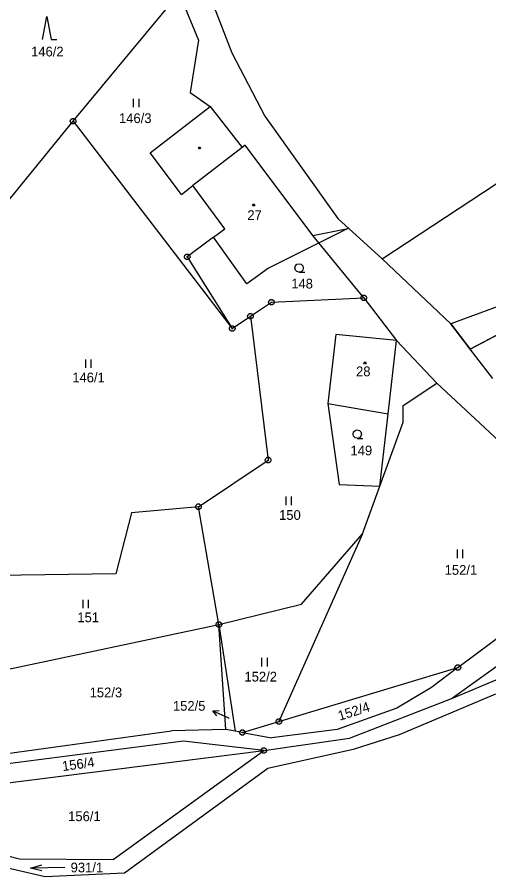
# Model space of a CAD drawing. Extents: x -580551 to -575069, y -1073031 to -1067931.
# Drawn here: x -576758.6 to -576676.1, y -1069901 to -1069750.7 of the extents above; entities that cross this region are included whole.
import ezdxf

# ---------------------------------------------------------------- set-up
doc = ezdxf.new("R2010")
doc.units = 0
for name, color, linetype in [('Druh pozemku', 7, 'Continuous'), ('Geodetické body', 7, 'Continuous'), ('Katastrální hranice', 7, 'Continuous'), ('Parcela', 7, 'Continuous'), ('Parcelní číslo', 7, 'Continuous'), ('Parcelní číslo_stavba', 7, 'Continuous'), ('Pomocná vrstva', 7, 'Continuous'), ('SR - hranice státu', 7, 'Continuous'), ('Vnitřní kresba', 7, 'Continuous'), ('Vrstva 6', 7, 'Continuous')]:
    doc.layers.add(name, color=color, linetype=linetype)

msp = doc.modelspace()

# ---------------------------------------------------------------- linework, layer by layer
at = {"layer": 'Druh pozemku'}
for p, q in [((-576738.33, -1069764.98), (-576738.33, -1069766.48)), ((-576737.33, -1069766.48), (-576737.33, -1069764.98)), ((-576746.71, -1069810.56), (-576746.71, -1069812.06)), ((-576745.71, -1069812.06), (-576745.71, -1069810.56)), ((-576711.66, -1069834.55), (-576711.66, -1069836.05)), ((-576710.66, -1069836.05), (-576710.66, -1069834.55)), ((-576681.66, -1069843.82), (-576681.66, -1069845.32)), ((-576680.66, -1069845.32), (-576680.66, -1069843.82)), ((-576747.18, -1069852.58), (-576747.18, -1069854.08)), ((-576746.18, -1069854.08), (-576746.18, -1069852.58)), ((-576715.88, -1069862.74), (-576715.88, -1069864.24)), ((-576714.88, -1069864.24), (-576714.88, -1069862.74)), ((-576750.31, -1069899.407), (-576756.31, -1069899.493))]:
    msp.add_line(p, q, dxfattribs=at)
for points in [[(-576754.19, -1069754.61), (-576753.44, -1069750.61), (-576752.69, -1069754.61), (-576751.69, -1069754.61)], [(-576709.32, -1069795.31), (-576709.7, -1069795.21), (-576709.97, -1069794.94), (-576710.07, -1069794.57), (-576709.97, -1069794.2), (-576709.7, -1069793.93), (-576709.33, -1069793.83), (-576708.96, -1069793.93), (-576708.69, -1069794.2), (-576708.59, -1069794.58), (-576708.69, -1069794.96), (-576708.96, -1069795.23), (-576709.34, -1069795.33), (-576708.34, -1069795.33)], [(-576699.14, -1069824.35), (-576699.52, -1069824.25), (-576699.79, -1069823.98), (-576699.89, -1069823.61), (-576699.79, -1069823.24), (-576699.52, -1069822.97), (-576699.15, -1069822.87), (-576698.78, -1069822.97), (-576698.51, -1069823.24), (-576698.41, -1069823.62), (-576698.51, -1069824), (-576698.78, -1069824.27), (-576699.16, -1069824.37), (-576698.16, -1069824.37)], [(-576754.303, -1069899.964), (-576756.31, -1069899.493), (-576754.317, -1069898.964)]]:
    msp.add_lwpolyline(points, dxfattribs=at)
for points in [[(-576726.65, -1069773.46), (-576726.56, -1069773.61), (-576726.65, -1069773.76), (-576726.83, -1069773.76), (-576726.92, -1069773.61), (-576726.83, -1069773.46)], [(-576717.18, -1069783.4), (-576717.09, -1069783.55), (-576717.18, -1069783.7), (-576717.36, -1069783.7), (-576717.45, -1069783.55), (-576717.36, -1069783.4)], [(-576697.71, -1069811.02), (-576697.62, -1069811.17), (-576697.71, -1069811.32), (-576697.89, -1069811.32), (-576697.98, -1069811.17), (-576697.89, -1069811.02)]]:
    msp.add_lwpolyline(points, close=True, dxfattribs=at)
at = {"layer": 'Geodetické body'}
for p, q in [((-576748.98, -1069768.89), (-576748.74, -1069768.89)), ((-576729, -1069792.64), (-576728.76, -1069792.64)), ((-576698.13, -1069799.81), (-576697.89, -1069799.81)), ((-576714.28, -1069800.56), (-576714.04, -1069800.56)), ((-576717.96, -1069803), (-576717.72, -1069803)), ((-576721.13, -1069805.15), (-576720.89, -1069805.15)), ((-576714.87, -1069828.16), (-576714.63, -1069828.16)), ((-576727.05, -1069836.32), (-576726.81, -1069836.32)), ((-576723.46, -1069856.9), (-576723.22, -1069856.9)), ((-576681.68, -1069864.43), (-576681.44, -1069864.43)), ((-576712.97, -1069873.86), (-576712.73, -1069873.86)), ((-576719.37, -1069875.79), (-576719.13, -1069875.79)), ((-576715.63, -1069878.94), (-576715.39, -1069878.94))]:
    msp.add_line(p, q, dxfattribs=at)
for points in [[(-576748.71, -1069768.41), (-576748.46, -1069768.59), (-576748.36, -1069768.88), (-576748.46, -1069769.17), (-576748.71, -1069769.35), (-576749.02, -1069769.35), (-576749.27, -1069769.17), (-576749.37, -1069768.88), (-576749.27, -1069768.59), (-576749.02, -1069768.41)], [(-576728.73, -1069792.16), (-576728.48, -1069792.34), (-576728.38, -1069792.63), (-576728.48, -1069792.92), (-576728.73, -1069793.1), (-576729.04, -1069793.1), (-576729.29, -1069792.92), (-576729.39, -1069792.63), (-576729.29, -1069792.34), (-576729.04, -1069792.16)], [(-576697.86, -1069799.33), (-576697.61, -1069799.51), (-576697.51, -1069799.8), (-576697.61, -1069800.09), (-576697.86, -1069800.27), (-576698.17, -1069800.27), (-576698.42, -1069800.09), (-576698.52, -1069799.8), (-576698.42, -1069799.51), (-576698.17, -1069799.33)], [(-576714.01, -1069800.08), (-576713.76, -1069800.26), (-576713.66, -1069800.55), (-576713.76, -1069800.84), (-576714.01, -1069801.02), (-576714.32, -1069801.02), (-576714.57, -1069800.84), (-576714.67, -1069800.55), (-576714.57, -1069800.26), (-576714.32, -1069800.08)], [(-576717.69, -1069802.52), (-576717.44, -1069802.7), (-576717.34, -1069802.99), (-576717.44, -1069803.28), (-576717.69, -1069803.46), (-576718, -1069803.46), (-576718.25, -1069803.28), (-576718.35, -1069802.99), (-576718.25, -1069802.7), (-576718, -1069802.52)], [(-576720.86, -1069804.67), (-576720.61, -1069804.85), (-576720.51, -1069805.14), (-576720.61, -1069805.43), (-576720.86, -1069805.61), (-576721.17, -1069805.61), (-576721.42, -1069805.43), (-576721.52, -1069805.14), (-576721.42, -1069804.85), (-576721.17, -1069804.67)], [(-576714.6, -1069827.68), (-576714.35, -1069827.86), (-576714.25, -1069828.15), (-576714.35, -1069828.44), (-576714.6, -1069828.62), (-576714.91, -1069828.62), (-576715.16, -1069828.44), (-576715.26, -1069828.15), (-576715.16, -1069827.86), (-576714.91, -1069827.68)], [(-576726.78, -1069835.84), (-576726.53, -1069836.02), (-576726.43, -1069836.31), (-576726.53, -1069836.6), (-576726.78, -1069836.78), (-576727.09, -1069836.78), (-576727.34, -1069836.6), (-576727.44, -1069836.31), (-576727.34, -1069836.02), (-576727.09, -1069835.84)], [(-576723.19, -1069856.42), (-576722.94, -1069856.6), (-576722.84, -1069856.89), (-576722.94, -1069857.18), (-576723.19, -1069857.36), (-576723.5, -1069857.36), (-576723.75, -1069857.18), (-576723.85, -1069856.89), (-576723.75, -1069856.6), (-576723.5, -1069856.42)], [(-576681.41, -1069863.95), (-576681.16, -1069864.13), (-576681.06, -1069864.42), (-576681.16, -1069864.71), (-576681.41, -1069864.89), (-576681.72, -1069864.89), (-576681.97, -1069864.71), (-576682.07, -1069864.42), (-576681.97, -1069864.13), (-576681.72, -1069863.95)], [(-576712.7, -1069873.38), (-576712.45, -1069873.56), (-576712.35, -1069873.85), (-576712.45, -1069874.14), (-576712.7, -1069874.32), (-576713.01, -1069874.32), (-576713.26, -1069874.14), (-576713.36, -1069873.85), (-576713.26, -1069873.56), (-576713.01, -1069873.38)], [(-576719.1, -1069875.31), (-576718.85, -1069875.49), (-576718.75, -1069875.78), (-576718.85, -1069876.07), (-576719.1, -1069876.25), (-576719.41, -1069876.25), (-576719.66, -1069876.07), (-576719.76, -1069875.78), (-576719.66, -1069875.49), (-576719.41, -1069875.31)], [(-576715.36, -1069878.46), (-576715.11, -1069878.64), (-576715.01, -1069878.93), (-576715.11, -1069879.22), (-576715.36, -1069879.4), (-576715.67, -1069879.4), (-576715.92, -1069879.22), (-576716.02, -1069878.93), (-576715.92, -1069878.64), (-576715.67, -1069878.46)]]:
    msp.add_lwpolyline(points, close=True, dxfattribs=at)
at = {"layer": 'Katastrální hranice'}
for p, q in [((-576674.95, -1069869.1), (-576691.8, -1069876.18)), ((-576691.8, -1069876.18), (-576699.84, -1069878.79)), ((-576699.84, -1069878.79), (-576714.77, -1069882.12)), ((-576714.77, -1069882.12), (-576739.85, -1069900.42)), ((-576753.74, -1069901.03), (-576766.39, -1069898.12)), ((-576739.85, -1069900.42), (-576753.74, -1069901.03))]:
    msp.add_line(p, q, dxfattribs=at)
at = {"layer": 'Parcela'}
for p, q in [((-576748.86, -1069768.89), (-576730.31, -1069746.58)), ((-576730.31, -1069746.58), (-576726.93, -1069754.75)), ((-576724.59, -1069747.91), (-576721.12, -1069756.95)), ((-576726.93, -1069754.75), (-576728.4, -1069763.88)), ((-576721.12, -1069756.95), (-576715.34, -1069768.01)), ((-576694.77, -1069792.96), (-576643.26, -1069759.05)), ((-576728.4, -1069763.88), (-576724.89, -1069766.32)), ((-576735.4, -1069774.46), (-576724.89, -1069766.32)), ((-576724.89, -1069766.32), (-576719.28, -1069773.48)), ((-576715.34, -1069768.01), (-576702.53, -1069785.94)), ((-576781.81, -1069809.35), (-576748.86, -1069768.89)), ((-576748.86, -1069768.89), (-576721.01, -1069805.15)), ((-576718.76, -1069773.11), (-576719.28, -1069773.48)), ((-576706.94, -1069788.87), (-576718.76, -1069773.11)), ((-576729.89, -1069781.72), (-576735.4, -1069774.46)), ((-576729.89, -1069781.72), (-576727.89, -1069780.17)), ((-576722.29, -1069787.7), (-576727.89, -1069780.17)), ((-576702.53, -1069785.94), (-576694.77, -1069792.96)), ((-576724.28, -1069789.2), (-576722.29, -1069787.7)), ((-576724.28, -1069789.2), (-576724.99, -1069789.73)), ((-576718.47, -1069797.36), (-576724.28, -1069789.2)), ((-576698.01, -1069799.81), (-576706.94, -1069788.87)), ((-576724.99, -1069789.73), (-576728.88, -1069792.64)), ((-576646.62, -1069791.48), (-576679.38, -1069808.74)), ((-576728.88, -1069792.64), (-576721.01, -1069805.15)), ((-576682.77, -1069804.33), (-576694.77, -1069792.96)), ((-576714.69, -1069794.58), (-576718.47, -1069797.36)), ((-576714.16, -1069800.56), (-576698.01, -1069799.81)), ((-576698.01, -1069799.81), (-576692.3, -1069807.26)), ((-576717.84, -1069803), (-576714.16, -1069800.56)), ((-576674.38, -1069801.23), (-576682.77, -1069804.33)), ((-576721.01, -1069805.15), (-576717.84, -1069803)), ((-576717.84, -1069803), (-576714.75, -1069828.16)), ((-576679.38, -1069808.74), (-576682.77, -1069804.33)), ((-576702.88, -1069806.21), (-576704.32, -1069818.27)), ((-576692.3, -1069807.26), (-576702.88, -1069806.21)), ((-576692.3, -1069807.26), (-576685.23, -1069814.74)), ((-576675.42, -1069813.89), (-576679.38, -1069808.74)), ((-576691.13, -1069818.6), (-576685.23, -1069814.74)), ((-576685.23, -1069814.74), (-576654.05, -1069843.8)), ((-576704.32, -1069818.27), (-576693.75, -1069820.07)), ((-576704.32, -1069818.27), (-576702.33, -1069832.44)), ((-576691.13, -1069821.52), (-576691.13, -1069818.6)), ((-576695.19, -1069832.71), (-576693.75, -1069820.07)), ((-576695.19, -1069832.71), (-576691.13, -1069821.52)), ((-576726.93, -1069836.32), (-576714.75, -1069828.16)), ((-576702.33, -1069832.44), (-576695.19, -1069832.71)), ((-576698.22, -1069841.05), (-576695.19, -1069832.71)), ((-576738.67, -1069837.36), (-576741.39, -1069848.08)), ((-576726.93, -1069836.32), (-576738.67, -1069837.36)), ((-576723.34, -1069856.9), (-576726.93, -1069836.32)), ((-576698.22, -1069841.05), (-576712.85, -1069873.86)), ((-576708.9, -1069853.34), (-576698.22, -1069841.05)), ((-576681.56, -1069864.43), (-576654.05, -1069843.8)), ((-576741.39, -1069848.08), (-576772.18, -1069848.51)), ((-576652.95, -1069848.59), (-576682.48, -1069869.82)), ((-576723.34, -1069856.9), (-576708.9, -1069853.34)), ((-576682.48, -1069869.82), (-576643.02, -1069853.07)), ((-576769.79, -1069866.75), (-576723.34, -1069856.9)), ((-576722.12, -1069875.27), (-576723.34, -1069856.9)), ((-576712.85, -1069873.86), (-576681.56, -1069864.43)), ((-576681.56, -1069864.43), (-576686.14, -1069867.93)), ((-576686.14, -1069867.93), (-576692.24, -1069871.53)), ((-576700.52, -1069876.78), (-576682.48, -1069869.82)), ((-576692.24, -1069871.53), (-576702.68, -1069875.27)), ((-576719.25, -1069875.79), (-576712.85, -1069873.86)), ((-576768.86, -1069880.6), (-576731.63, -1069875.53)), ((-576722.12, -1069875.27), (-576731.63, -1069875.53)), ((-576720.52, -1069875.56), (-576722.12, -1069875.27)), ((-576719.25, -1069875.79), (-576720.52, -1069875.56)), ((-576719.25, -1069875.79), (-576714.13, -1069876.72)), ((-576702.68, -1069875.27), (-576714.13, -1069876.72)), ((-576729.56, -1069877.29), (-576768.32, -1069882.29)), ((-576715.51, -1069878.94), (-576729.56, -1069877.29)), ((-576715.51, -1069878.94), (-576700.52, -1069876.78)), ((-576771.28, -1069885.96), (-576715.51, -1069878.94)), ((-576741.85, -1069897.99), (-576715.51, -1069878.94)), ((-576767.99, -1069895.36), (-576758.22, -1069897.87)), ((-576758.22, -1069897.87), (-576741.85, -1069897.99))]:
    msp.add_line(p, q, dxfattribs=at)
msp.add_lwpolyline([(-576706.94, -1069788.87), (-576700.773, -1069787.676), (-576714.69, -1069794.58)], dxfattribs=at)
at = {"layer": 'Pomocná vrstva'}
for p in [(-576724.421, -1069871.996), (-576721.56, -1069873.32)]:
    msp.add_line(p, (-576721.7, -1069873.26), dxfattribs=at)
msp.add_lwpolyline([(-576723.725, -1069872.871), (-576724.421, -1069871.996), (-576723.303, -1069871.964)], dxfattribs=at)
at = {"layer": 'SR - hranice státu'}
for p, q in [((-576748.86, -1069768.89), (-576730.31, -1069746.58)), ((-576781.81, -1069809.35), (-576748.86, -1069768.89))]:
    msp.add_line(p, q, dxfattribs=at)
for points in [[(-576730.31, -1069746.58), (-576724.59, -1069747.91), (-576721.12, -1069756.95), (-576715.34, -1069768.01), (-576702.53, -1069785.94), (-576694.77, -1069792.96)], [(-576679.38, -1069808.74), (-576646.62, -1069791.48), (-576645.63, -1069788.55), (-576638.2, -1069784.83), (-576637.65, -1069787.3)], [(-576694.77, -1069792.96), (-576682.77, -1069804.33), (-576679.38, -1069808.74)]]:
    msp.add_lwpolyline(points, dxfattribs=at)
at = {"layer": 'Vnitřní kresba'}
for p, q in [((-576719.28, -1069773.48), (-576727.89, -1069780.17)), ((-576693.75, -1069820.07), (-576692.3, -1069807.26))]:
    msp.add_line(p, q, dxfattribs=at)
at = {"layer": 'Vrstva 6'}
msp.add_line((-576723.34, -1069856.9), (-576720.52, -1069875.56), dxfattribs=at)

# ---------------------------------------------------------------- texts
at = {"layer": 'Parcelní číslo'}
for s, height, p in [('146/2', 1.7, (-576756.207, -1069757.58)), ('146/3', 1.7, (-576740.829, -1069769.23)), ('148', 1.7, (-576710.695, -1069798.16)), ('146/1', 1.7, (-576749.005, -1069814.57)), ('149', 1.7, (-576700.337, -1069827.34)), ('150', 1.7, (-576712.822, -1069838.62)), ('152/1', 1.7, (-576683.861, -1069848.22)), ('151', 1.7, (-576748.111, -1069856.51)), ('152/2', 1.7, (-576718.884, -1069866.88)), ('152/3', 1.7, (-576745.965, -1069869.64)), ('152/5', 0.1, (-576721.751, -1069873.32)), ('156/1', 1.7, (-576749.726, -1069891.3)), ('931/1', 1.7, (-576749.292, -1069900.25))]:
    msp.add_text(s, height=height, dxfattribs=at).set_placement(p)
for s, rotation, p in [('152/4', 17.7044, (-576702.215, -1069873.75)), ('156/4', 7.79223, (-576750.658, -1069882.555))]:
    msp.add_text(s, height=1.7, rotation=rotation, dxfattribs=at).set_placement(p)
at = {"layer": 'Parcelní číslo_stavba'}
for s, p in [('27', (-576718.376, -1069786.18)), ('28', (-576699.359, -1069813.5))]:
    msp.add_text(s, height=1.7, dxfattribs=at).set_placement(p)
at = {"layer": 'Pomocná vrstva'}
msp.add_text('152/5', height=1.7, dxfattribs=at).set_placement((-576731.398, -1069871.99))

doc.saveas('drawing.dxf')
